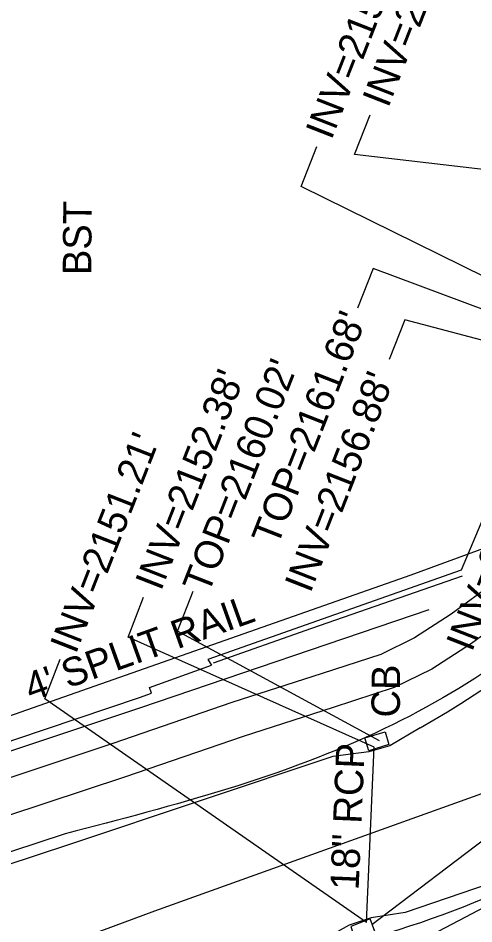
# Model space of a CAD drawing. Extents: x 945964 to 948456, y 631061 to 636061.
# Drawn here: x 946484.6 to 946548.6, y 632741.7 to 632869 of the extents above; entities that cross this region are included whole.
import ezdxf

# ---------------------------------------------------------------- set-up
doc = ezdxf.new("R2010")
doc.units = 0
for name, color, linetype in [('Exist Other Culture Fence Line', 7, 'Continuous'), ('Exist Other Culture Fence Line Text', 7, 'Continuous'), ('Exist Roads Curbs', 7, 'Continuous'), ('Exist Roads EOP', 7, 'Continuous'), ('Exist Roads EOP Other', 7, 'Continuous'), ('Exist Roads EOP Other Text', 7, 'Continuous'), ('Exist Structure Minor Catch Basin', 7, 'Continuous'), ('Exist Structure Minor Catch Basin Text', 7, 'Continuous'), ('Exist Structure Minor Catch Basin Top Elevation', 7, 'Continuous'), ('Exist Structure Minor Pipes RCP 15 Inch Invert', 7, 'Continuous'), ('Exist Structure Minor Pipes RCP 18 Inch', 7, 'Continuous'), ('Exist Structure Minor Pipes RCP 18 Inch Invert', 7, 'Continuous'), ('Exist Structure Minor Pipes RCP 18 Inch Text', 7, 'Continuous'), ('Exist Structure Minor Storm Sewer Manhole Top Elevation', 7, 'Continuous'), ('Exist Utilities Power UG Cable SUE', 7, 'Continuous'), ('Exist Utilities Telephone UG FO SUE', 7, 'Continuous'), ('Exist Utilities Water UG Line SUE', 7, 'Continuous')]:
    doc.layers.add(name, color=color, linetype=linetype)

msp = doc.modelspace()

# ---------------------------------------------------------------- linework, layer by layer
at = {"layer": 'Exist Other Culture Fence Line'}
msp.add_lwpolyline([(946542.28, 632785.83), (946501.77, 632772.1), (946442.96, 632752.47), (946391.56, 632735.6)], dxfattribs=at)
at = {"layer": 'Exist Roads Curbs'}
for points in [[(946512.05, 632778.38), (946525.83, 632783.25), (946546.97, 632790.64)], [(946491.19, 632754.39), (946449.9, 632740.8), (946410.24, 632727.44), (946400.09, 632724.02), (946398.12, 632723.45)]]:
    msp.add_lwpolyline(points, dxfattribs=at)
for points in [[(946597.91, 632894.22), (946599.24, 632888.62), (946600.27, 632883.63), (946601.11, 632877.34), (946599.35, 632845.41), (946591, 632824.04), (946570.08, 632793.78), (946536.06, 632769.16), (946491.19, 632754.39)], [(946627.3, 632885.56), (946628.01, 632879.17), (946627.89, 632857.01), (946620.51, 632823.66), (946604.53, 632793.59), (946576.99, 632762.41), (946551.48, 632745.94), (946527.29, 632737.67)], [(946601.93, 632772.67), (946579.15, 632743.42), (946547.53, 632710.06), (946519.46, 632682.69), (946496.47, 632656.95), (946474.49, 632624.89), (946453.03, 632584.16), (946438.45, 632541.43), (946430.15, 632490.73), (946428.83, 632457.38), (946430.2, 632433.68), (946432.57, 632412.52), (946425.74, 632395.61), (946417.04, 632384.69)]]:
    msp.add_spline(points, degree=3, dxfattribs=at)
at = {"layer": 'Exist Roads EOP'}
for points in [[(946457.98, 632885.59), (946482.87, 632893.93), (946508.17, 632902.23), (946536.62, 632910.93), (946551.72, 632915.33), (946555.91, 632900.49), (946561.96, 632880.62), (946565.43, 632869.8), (946567.1, 632862.49), (946567.6, 632857.42), (946567.48, 632852.56), (946566.64, 632845.18), (946564.18, 632838.33), (946559.78, 632828.76), (946554.94, 632814.79), (946551.94, 632803.63), (946546.8, 632791.44), (946511.22, 632778.87), (946511.76, 632778.07)], [(946360.36, 632745.09), (946360.81, 632744.2), (946362.58, 632744.95), (946368.15, 632732.35), (946383.83, 632737.73), (946384.56, 632735.86), (946390.18, 632737.73), (946390.68, 632736.52), (946408.72, 632742.55), (946422.32, 632747.58), (946438.92, 632752.86), (946453.03, 632757.25), (946467.57, 632761.91), (946484.29, 632767.7), (946501.66, 632773.54), (946503.34, 632774.16), (946503.05, 632774.92), (946511.76, 632778.07)], [(946541.03, 632769.28), (946536.78, 632766.76), (946533.82, 632765.92), (946528.8, 632765.25), (946491.79, 632752.89), (946450.33, 632739.22), (946410.88, 632726.15), (946406.42, 632723.56), (946403.47, 632722.63)], [(946550.72, 632747.33), (946538.92, 632743.34), (946534.18, 632742.6), (946531.1, 632741.53), (946526.64, 632739.08), (946484.59, 632725.12), (946442.49, 632711.17), (946418.22, 632702.92), (946413.45, 632701.7), (946410.52, 632700.21), (946407.04, 632696.87)]]:
    msp.add_lwpolyline(points, dxfattribs=at)
msp.add_ellipse((946480.04, 632878.97), major_axis=(64.38, 107.78), ratio=0.999484, start_param=4.187765, end_param=4.752276, dxfattribs=at)
msp.add_spline([(946603.2, 632771.71), (946580.04, 632742.14), (946547.72, 632708.15), (946520.62, 632681.67), (946497.88, 632656.28), (946475.52, 632623.93), (946454.54, 632583.75), (946439.95, 632540.86), (946431.6, 632490.76), (946430.35, 632457.42), (946431.68, 632434.16), (946433.99, 632412.2), (946427.3, 632395.46), (946417.68, 632383.18)], degree=3, dxfattribs=at)
at = {"layer": 'Exist Roads EOP Other'}
for points in [[(946551.55, 632789.72), (946545.4, 632785.22), (946540.23, 632781.89), (946535.51, 632779.59), (946527.27, 632776.88), (946514.61, 632772.81), (946497.91, 632767.09), (946481.4, 632761.6)], [(946554.7, 632785.83), (946548.24, 632781.1), (946542.69, 632777.53), (946537.4, 632774.95), (946528.81, 632772.12), (946516.18, 632768.06), (946499.51, 632762.35), (946482.96, 632756.84)]]:
    msp.add_lwpolyline(points, dxfattribs=at)
at = {"layer": 'Exist Structure Minor Catch Basin'}
for points in [[(946533.3, 632767.87), (946536.14, 632768.69), (946536.65, 632766.91), (946533.84, 632766.03), (946533.3, 632767.87)], [(946534.05, 632742.44), (946531.31, 632741.38), (946531.83, 632739.7), (946534.69, 632740.65), (946534.05, 632742.44)]]:
    msp.add_lwpolyline(points, dxfattribs=at)
at = {"layer": 'Exist Structure Minor Catch Basin Top Elevation'}
msp.add_lwpolyline([(946535.32, 632767.43), (946506.98, 632782.87), (946509.17, 632788.46)], dxfattribs=at)
at = {"layer": 'Exist Structure Minor Pipes RCP 18 Inch'}
for p, q in [((946603.78, 632794.57), (946534.28, 632741.58)), ((946533.53, 632741.9), (946534.59, 632766.53))]:
    msp.add_line(p, q, dxfattribs=at)
at = {"layer": 'Exist Structure Minor Pipes RCP 18 Inch Invert'}
for points in [[(946579.61, 632844.23), (946531.84, 632849.81), (946534.03, 632855.4)], [(946582.64, 632816.59), (946524.34, 632845.34), (946526.52, 632850.93)], [(946583.34, 632814.83), (946538.89, 632826.58), (946536.7, 632821)], [(946534.59, 632766.53), (946500.04, 632782.03), (946502.22, 632787.61)], [(946533.53, 632741.9), (946488.33, 632773.33), (946490.51, 632778.92)]]:
    msp.add_lwpolyline(points, dxfattribs=at)
at = {"layer": 'Exist Structure Minor Storm Sewer Manhole Top Elevation'}
msp.add_lwpolyline([(946582.97, 632815.69), (946534.44, 632833.8), (946532.25, 632828.21)], dxfattribs=at)
at = {"layer": 'Exist Utilities Power UG Cable SUE'}
msp.add_lwpolyline([(946358.83, 632671.87), (946409.81, 632694.19), (946491.07, 632719.59), (946512.34, 632726.76), (946527.94, 632732.44), (946563.12, 632750.98), (946591.54, 632775.57), (946597.73, 632780.43), (946610.71, 632793.64), (946619, 632807.83), (946625.48, 632824.38), (946631.48, 632842.49), (946635.14, 632865.8), (946629.47, 632896.55)], dxfattribs=at)
at = {"layer": 'Exist Utilities Telephone UG FO SUE'}
msp.add_lwpolyline([(946343.46, 632690.97), (946424.89, 632714.31), (946503.77, 632743.56), (946582.19, 632771.71)], dxfattribs=at)
at = {"layer": 'Exist Utilities Water UG Line SUE'}
msp.add_lwpolyline([(946450.51, 632206.48), (946434.39, 632257.32), (946406.99, 632342.82), (946396.29, 632375.97), (946378.9, 632423.81), (946365.5, 632463.34), (946339.7, 632545.71), (946360.27, 632568.18), (946378.23, 632596.81), (946392.83, 632624.5), (946375.23, 632673.95), (946369.96, 632698.61), (946371.67, 632730.29), (946403.03, 632742.7), (946539.78, 632790.77), (946609.96, 632816.5), (946596.43, 632867.38), (946587.53, 632902.31), (946563.28, 632978.1), (946529.52, 633075.74), (946498.27, 633161.68), (946472.52, 633239.25)], dxfattribs=at)

# ---------------------------------------------------------------- texts
at = {"layer": 'Exist Other Culture Fence Line Text'}
msp.add_text("4' SPLIT RAIL", height=4, rotation=19.7169, dxfattribs=at).set_placement((946486.39, 632772.93))
at = {"layer": 'Exist Roads EOP Other Text'}
msp.add_text('BST', height=4, rotation=89.5187, dxfattribs=at).set_placement((946494.85, 632832.86))
at = {"layer": 'Exist Structure Minor Catch Basin Text'}
msp.add_text('CB', height=4, rotation=89.5187, dxfattribs=at).set_placement((946538.19, 632770.71))
at = {"layer": 'Exist Structure Minor Catch Basin Top Elevation'}
msp.add_text("TOP=2160.02'", height=4, rotation=68.6189, dxfattribs=at).set_placement((946511.31, 632787.91))
at = {"layer": 'Exist Structure Minor Pipes RCP 15 Inch Invert'}
msp.add_text("INV=2152.25'", height=4, rotation=68.6189, dxfattribs=at).set_placement((946548.31, 632779.8))
at = {"layer": 'Exist Structure Minor Pipes RCP 18 Inch Invert'}
for s, p in [("INV=2157.35'", (946536.55, 632856.24)), ("INV=2156.98'", (946528.58, 632851.73)), ("INV=2152.38'", (946504.65, 632788.37)), ("INV=2156.88'", (946525.63, 632788.07)), ("INV=2151.21'", (946492.69, 632779.51))]:
    msp.add_text(s, height=4, rotation=68.6189, dxfattribs=at).set_placement(p)
at = {"layer": 'Exist Structure Minor Pipes RCP 18 Inch Text'}
msp.add_text('18" RCP', height=4, rotation=87.5337, dxfattribs=at).set_placement((946532.4, 632746.42))
at = {"layer": 'Exist Structure Minor Storm Sewer Manhole Top Elevation'}
msp.add_text("TOP=2161.68'", height=4, rotation=68.6189, dxfattribs=at).set_placement((946521, 632794.64))

doc.saveas('drawing.dxf')
